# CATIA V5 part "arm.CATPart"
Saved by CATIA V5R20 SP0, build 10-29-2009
Part number: Arm
Bounding box of the stored display mesh (mm): x -25 to 25, y -25 to 105, z 0 to 25
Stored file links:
  D:\OneDrive\OneDrive - 한양대학교\문서\Teaching\2021\CAD\Final Exam\oscillation motion\arm.CATPart
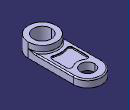
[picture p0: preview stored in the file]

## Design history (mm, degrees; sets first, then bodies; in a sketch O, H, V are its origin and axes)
Body1 (main body)
  Sketch1 on xy-plane, origin (0, 0, 0), H (1, 0, 0), V (0, 1, 0)
    arc A1 centre (0, 80) radius 25 from (25, 80) to (-25, 80) ccw
    arc A2 centre (0, 0) radius 25 from (-25, 0) to (25, 0) ccw
    point P2 (0, 0)
    line L1 (-25, 80) -> (-25, 0)
    point P4 (-25, 0)
    line L2 (25, 80) -> (25, 0)
    point P6 (25, 0)
    point P7 (-25, 0)
    point P8 (25, 0)
    circle A3 centre (0, 80) radius 12.5
    distance A1 A2 = 130
    radius A1 = 25
    radius A3 = 12.5
    coincidence: P4 A2, P6 A2, L2 P8, L1 P7, P2 V, P4 P7, P6 P8
    vertical: L1 V, L2 V
    tangency: A1 L1, L2 A1, L1 A2, A2 L2
    concentricity: A3 A1
  Pad1: profile Sketch1, direction (0, 0, 1), length 13
  Sketch2 on end face of Pad1, origin (0, 0, 13), H (1, 0, 0), V (0, 1, 0)
    circle A1 centre (0, 0) radius 25
    reference projected arc E1 centre (0, 0) radius 25 from (-25, 0) to (25, 0) ccw from edge [face of Pad1 from Sketch1.A2 | end face of Pad1]
    radius A1 = 25
    concentricity: A1 E1
  Pad2: profile Sketch2, direction (0, 0, 1), length 12
  Sketch3 on end face of Pad2, origin (0, 0, 25), H (1, 0, 0), V (0, 1, 0)
    circle A1 centre (0, 0) radius 16
    reference projected circle E1 centre (0, 0) radius 25 from edge [face of Pad2 from Sketch2.A1 | end face of Pad2]
    radius A1 = 16
    concentricity: A1 E1
  Pocket1: profile Sketch3, direction (0, 0, -1), length 25
  Fillet1: radius 2, on edge [end face of Pad1 | face of Pad2 from Sketch2.A1]; edge [face of Pad1 from Sketch1.L1 | end face of Pad1]
  Sketch4 on end face of Pad1, origin (0, 0, 13), H (1, 0, 0), V (0, 1, 0)
    arc A1 centre (0, 0) radius 33 from (11.7237, 30.8473) to (-11.7237, 30.8473) ccw
    arc A2 centre (0, 80) radius 18.5 from (-10.6277, 64.8573) to (10.6277, 64.8573) ccw
    line L1 (-18.5, 60.7646) -> (-18.5, 35.5211)
    line L2 (18.5, 60.7646) -> (18.5, 35.5211)
    reference projected circle E1 centre (0, 80) radius 12.5 from edge [end face of Pad1 | face of Pad1 from Sketch1.A3]
    reference projected circle E2 centre (0, 0) radius 16 from edge [end face of Pad2 | face of Pocket1 from Sketch3.A1]
    arc A3 centre (13.5, 60.7646) radius 5 from (10.6277, 64.8573) to (18.5, 60.7646) cw
    arc A4 centre (-13.5, 60.7646) radius 5 from (-10.6277, 64.8573) to (-18.5, 60.7646) ccw
    arc A5 centre (-13.5, 35.5211) radius 5 from (-18.5, 35.5211) to (-11.7237, 30.8473) ccw
    arc A6 centre (13.5, 35.5211) radius 5 from (11.7237, 30.8473) to (18.5, 35.5211) ccw
    radius A2 = 18.5
    radius A1 = 33
    radius A3 = 5
    radius A4 = 5
    radius A5 = 5
    radius A6 = 5
    vertical: L1 V, L2 V
    concentricity: A2 E1, A1 E2
    tangency: L2 A2, L1 A2, A3 A2, A3 L2, A4 A2, A4 L1, A5 L1, A5 A1, A6 A1, A6 L2
  Pocket2: profile Sketch4, direction (0, 0, -1), length 2
  Fillet2: radius 1, on edge [face of Pocket2 from Sketch4.L2 | end face of Pocket2]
